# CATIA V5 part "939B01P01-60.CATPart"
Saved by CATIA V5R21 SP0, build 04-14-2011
Part number: 939B01P01-60
Bounding box of the stored display mesh (mm): x -17.1 to 17.1, y -76.2 to 76.2, z -4.4 to 55.6
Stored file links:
  C:\Users\ALI OZGUN\Desktop\alhan\939B01P01-60.CATPart
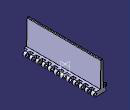
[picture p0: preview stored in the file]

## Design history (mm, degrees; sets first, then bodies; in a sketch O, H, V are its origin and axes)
Body1 (main body)
  Sketch1 on zx-plane, origin (0, 0, 0), H (-1, 0, 0), V (0, 0, 1)
    construction line L1 (-12.7, 0) -> (12.7, 0)
    point P1 (-12.7, 0)
    line L2 (-12.7, 4.4) -> (12.7, 4.4)
    line L3 (12.7, -4.4) -> (-12.7, -4.4)
    arc A1 centre (12.7, 0) radius 4.4 from (12.7, 4.4) to (12.7, -4.4) cw
    arc A2 centre (-12.7, 0) radius 4.4 from (-12.7, -4.4) to (-12.7, 4.4) cw
    distance L1 L2 = 4.4
    length L1 = 25.4
    distance P1 V = 12.7
    coincidence: P1 H
    horizontal: L1 H
    tangency: A1 L2, A2 L2, A1 L3, A2 L3
  Pad1: profile Sketch1, direction (0, 1, 0), length 76.2, mirrored extent
  Sketch2 on face of Pad1 from Sketch1.L2, origin (0, 0, 4.4), H (1, 0, 0), V (0, 1, 0)
    line L1 (-22.3127, -63.5) -> (-9.75, -63.5)
    line L2 (-9.75, -63.5) -> (-9.75, -70.6)
    line L3 (-9.75, -70.6) -> (-22.3127, -70.6)
    line L4 (-22.3127, -70.6) -> (-22.3127, -63.5)
    line L5 (24.6678, -76.95) -> (9.75, -76.95)
    line L6 (9.75, -76.95) -> (9.75, -69.85)
    line L7 (9.75, -69.85) -> (24.6678, -69.85)
    line L8 (24.6678, -69.85) -> (24.6678, -76.95)
    reference projected line E1 (-12.7, -76.2) -> (12.7, -76.2) from edge [start face of Pad1 | face of Pad1 from Sketch1.L2]
    reference projected line E2 (-12.7, -76.2) -> (12.7, -76.2) from edge [start face of Pad1 | face of Pad1 from Sketch1.L2]
    distance L3 E1 = 5.6
    length L4 = 7.1
    distance L7 L5 = 7.1
    distance L5 E2 = 0.75
    distance L2 L6 = 19.5
    distance L2 V = 9.75
    horizontal: L1 H, L3 H, L5 H, L7 H
    vertical: L2 V, L4 V, L6 V, L8 V
  Pocket1: profile Sketch2, direction (0, 0, -1), length 76.2
  RectPattern1: of Pocket1, direction 1 instances 12, spacing 12.7, along axis of face of Pad1 from Sketch1.A2
  Sketch3 on face of Pad1 from Sketch1.L3, origin (0, 0, -4.4), H (1, 0, 0), V (0, -1, 0)
    line L1 (-6.5, -54.6) -> (6.5, -54.6)
    line L2 (6.5, -54.6) -> (6.5, -73.7)
    line L3 (6.5, -73.7) -> (-6.5, -73.7)
    line L4 (-6.5, -73.7) -> (-6.5, -54.6)
    construction line L5 (-4.5, -51.1) -> (4.5, -51.1)
    point P5 (-4.5, -51.1)
    line L6 (-4.5, -49.6) -> (4.5, -49.6)
    line L7 (4.5, -52.6) -> (-4.5, -52.6)
    arc A1 centre (4.5, -51.1) radius 1.5 from (4.5, -49.6) to (4.5, -52.6) cw
    arc A2 centre (-4.5, -51.1) radius 1.5 from (-4.5, -52.6) to (-4.5, -49.6) cw
    reference projected line E1 (12.7, -76.2) -> (-12.7, -76.2) from edge [face of Pad1 from Sketch1.L3 | end face of Pad1]
    distance L5 L6 = 1.5
    distance L1 L3 = 19.1
    distance L4 L2 = 13
    distance L4 V = 6.5
    distance E1 L3 = 2.5
    distance P5 V = 4.5
    length L5 = 9
    distance L7 L1 = 2
    horizontal: L1 H, L3 H, L5 H
    vertical: L2 V, L4 V
    tangency: A1 L6, A2 L6, A1 L7, A2 L7
  Pocket2: profile Sketch3, direction (0, 0, 1), length 6
  RectPattern2: of Pocket2, direction 1 instances 6, spacing 25.8, along axis of face of Pad1 from Sketch1.A2 reversed
  Sketch4 on zx-plane, origin (0, 0, 0), H (-1, 0, 0), V (0, 0, 1)
    circle A1 centre (12.7, 0) radius 2.3
    point P1 (12.7, 0)
    circle A2 centre (-12.7, 0) radius 2.3
    point P2 (-12.7, 0)
    reference projected arc E1 centre (12.7, 0) radius 4.4 from (12.7, -4.4) to (12.7, 4.4) ccw from edge [face of RectPattern1 | face of Pad1 from Sketch1.A1]
    reference projected arc E2 centre (-12.7, 0) radius 4.4 from (-12.7, 4.4) to (-12.7, -4.4) ccw from edge [face of Pad1 from Sketch1.A2 | end face of Pad1]
    radius A1 = 2.3
    radius A2 = 2.3
    coincidence: P1 H, P2 H
    concentricity: P1 E1, A2 E2
  Pocket3: profile Sketch4, direction (0, -1, 0), length 97.8, mirrored extent
  Body2
    Solid1: linked copy from another document
    Symmetry1: Reference yz-plane, ToTransfor Solid1
    Translate1: Direction edge [face of Pocket1 from Sketch2.L2 | face of Pad1 from Sketch1.L3], Length 6.35, ToTransfor Symmetry1
    Body3
      Sketch5 on face of RectPattern1, origin (9.75, 0, 0), H (0, 1, 0), V (0, 0, 1)
      Pad2: profile Sketch5, direction (1, 0, 0), length 12
      Sketch6 on face of Pad2, origin (0, 69.85, 0), H (-1, 0, 0), V (0, 0, 1)
        point P2 (-21.75, 4.4)
        arc A1 centre (-16.4898, 1.5645) radius 9 from (-9.75, -4.4) to (-7.9481, 4.4) ccw
        point P8 (-21.75, 4.4)
        construction line L1 (-9.75, 4.4) -> (-21.75, 4.4)
        line L2 (-7.9481, 4.4) -> (-21.75, 4.4)
        line L3 (-9.75, -4.4) -> (-21.75, -4.4)
        line L4 (-21.75, -4.4) -> (-21.75, 4.4)
        radius A1 = 9
        coincidence: P2 P8
      Pad3: profile Sketch6, direction (0, 1, 0), up to face of Pad2
      RectPattern3: of the body so far, direction 1 instances 12, spacing 12.7, along edge [face of Pad3 | face of Pad3] reversed
    Add1: tool Body3
  Remove1: tool Body2
  Sketch7 on zx-plane, origin (0, 0, 0), H (-1, 0, 0), V (0, 0, 1)
    projected line E1 (7.9481, 4.4) -> (-12.7, 4.4) from edge [face of Pad1 from Sketch1.L2 | end face of Pad1]
    projected line E2 (3.2, 4.4) -> (-3.2, 4.4) from edge [face of Pad1 from Sketch1.L2 | end face of Pad1]
    point P3 (-3.2, 4.4)
    line L1 (-3.2, 4.4) -> (-2, 55.6)
    point P4 (-2, 55.6)
    line L2 (-2, 55.6) -> (2, 55.6)
    line L3 (2, 55.6) -> (3.2, 4.4)
    reference projected line E3 (-12.7, -4.4) -> (12.7, -4.4) from edge [face of Pad1 from Sketch1.L3 | end face of Pad1]
    distance L2 E3 = 60
    distance P3 V = 3.2
    distance P4 V = 2
    coincidence: P3 E1, P3 L1
    horizontal: L2 H
    symmetry: L1 L3 V
  Pad4: profile Sketch7, direction (0, 1, 0), length 76.2, mirrored extent
  Fillet1: radius 1, on edge [face of Pad4 from Sketch7.L2 | face of Pad4 from Sketch7.L3]; edge [face of Pad4 from Sketch7.L1 | face of Pad4 from Sketch7.L2]
Body4
  Solid2: linked copy from another document
  Translate2: Direction yz-plane, Length 25.4, ToTransfor Solid2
